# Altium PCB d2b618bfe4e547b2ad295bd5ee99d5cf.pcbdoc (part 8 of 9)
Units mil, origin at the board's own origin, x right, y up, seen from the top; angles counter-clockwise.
Board outline 5129 x 4161 mil, 8 copper layers (Top Layer, GND1, 内层2, VCC, 内层4, Inner5, GND2, Bottom Layer); 491 components, 452 nets, 2562 pads, 1124 vias.
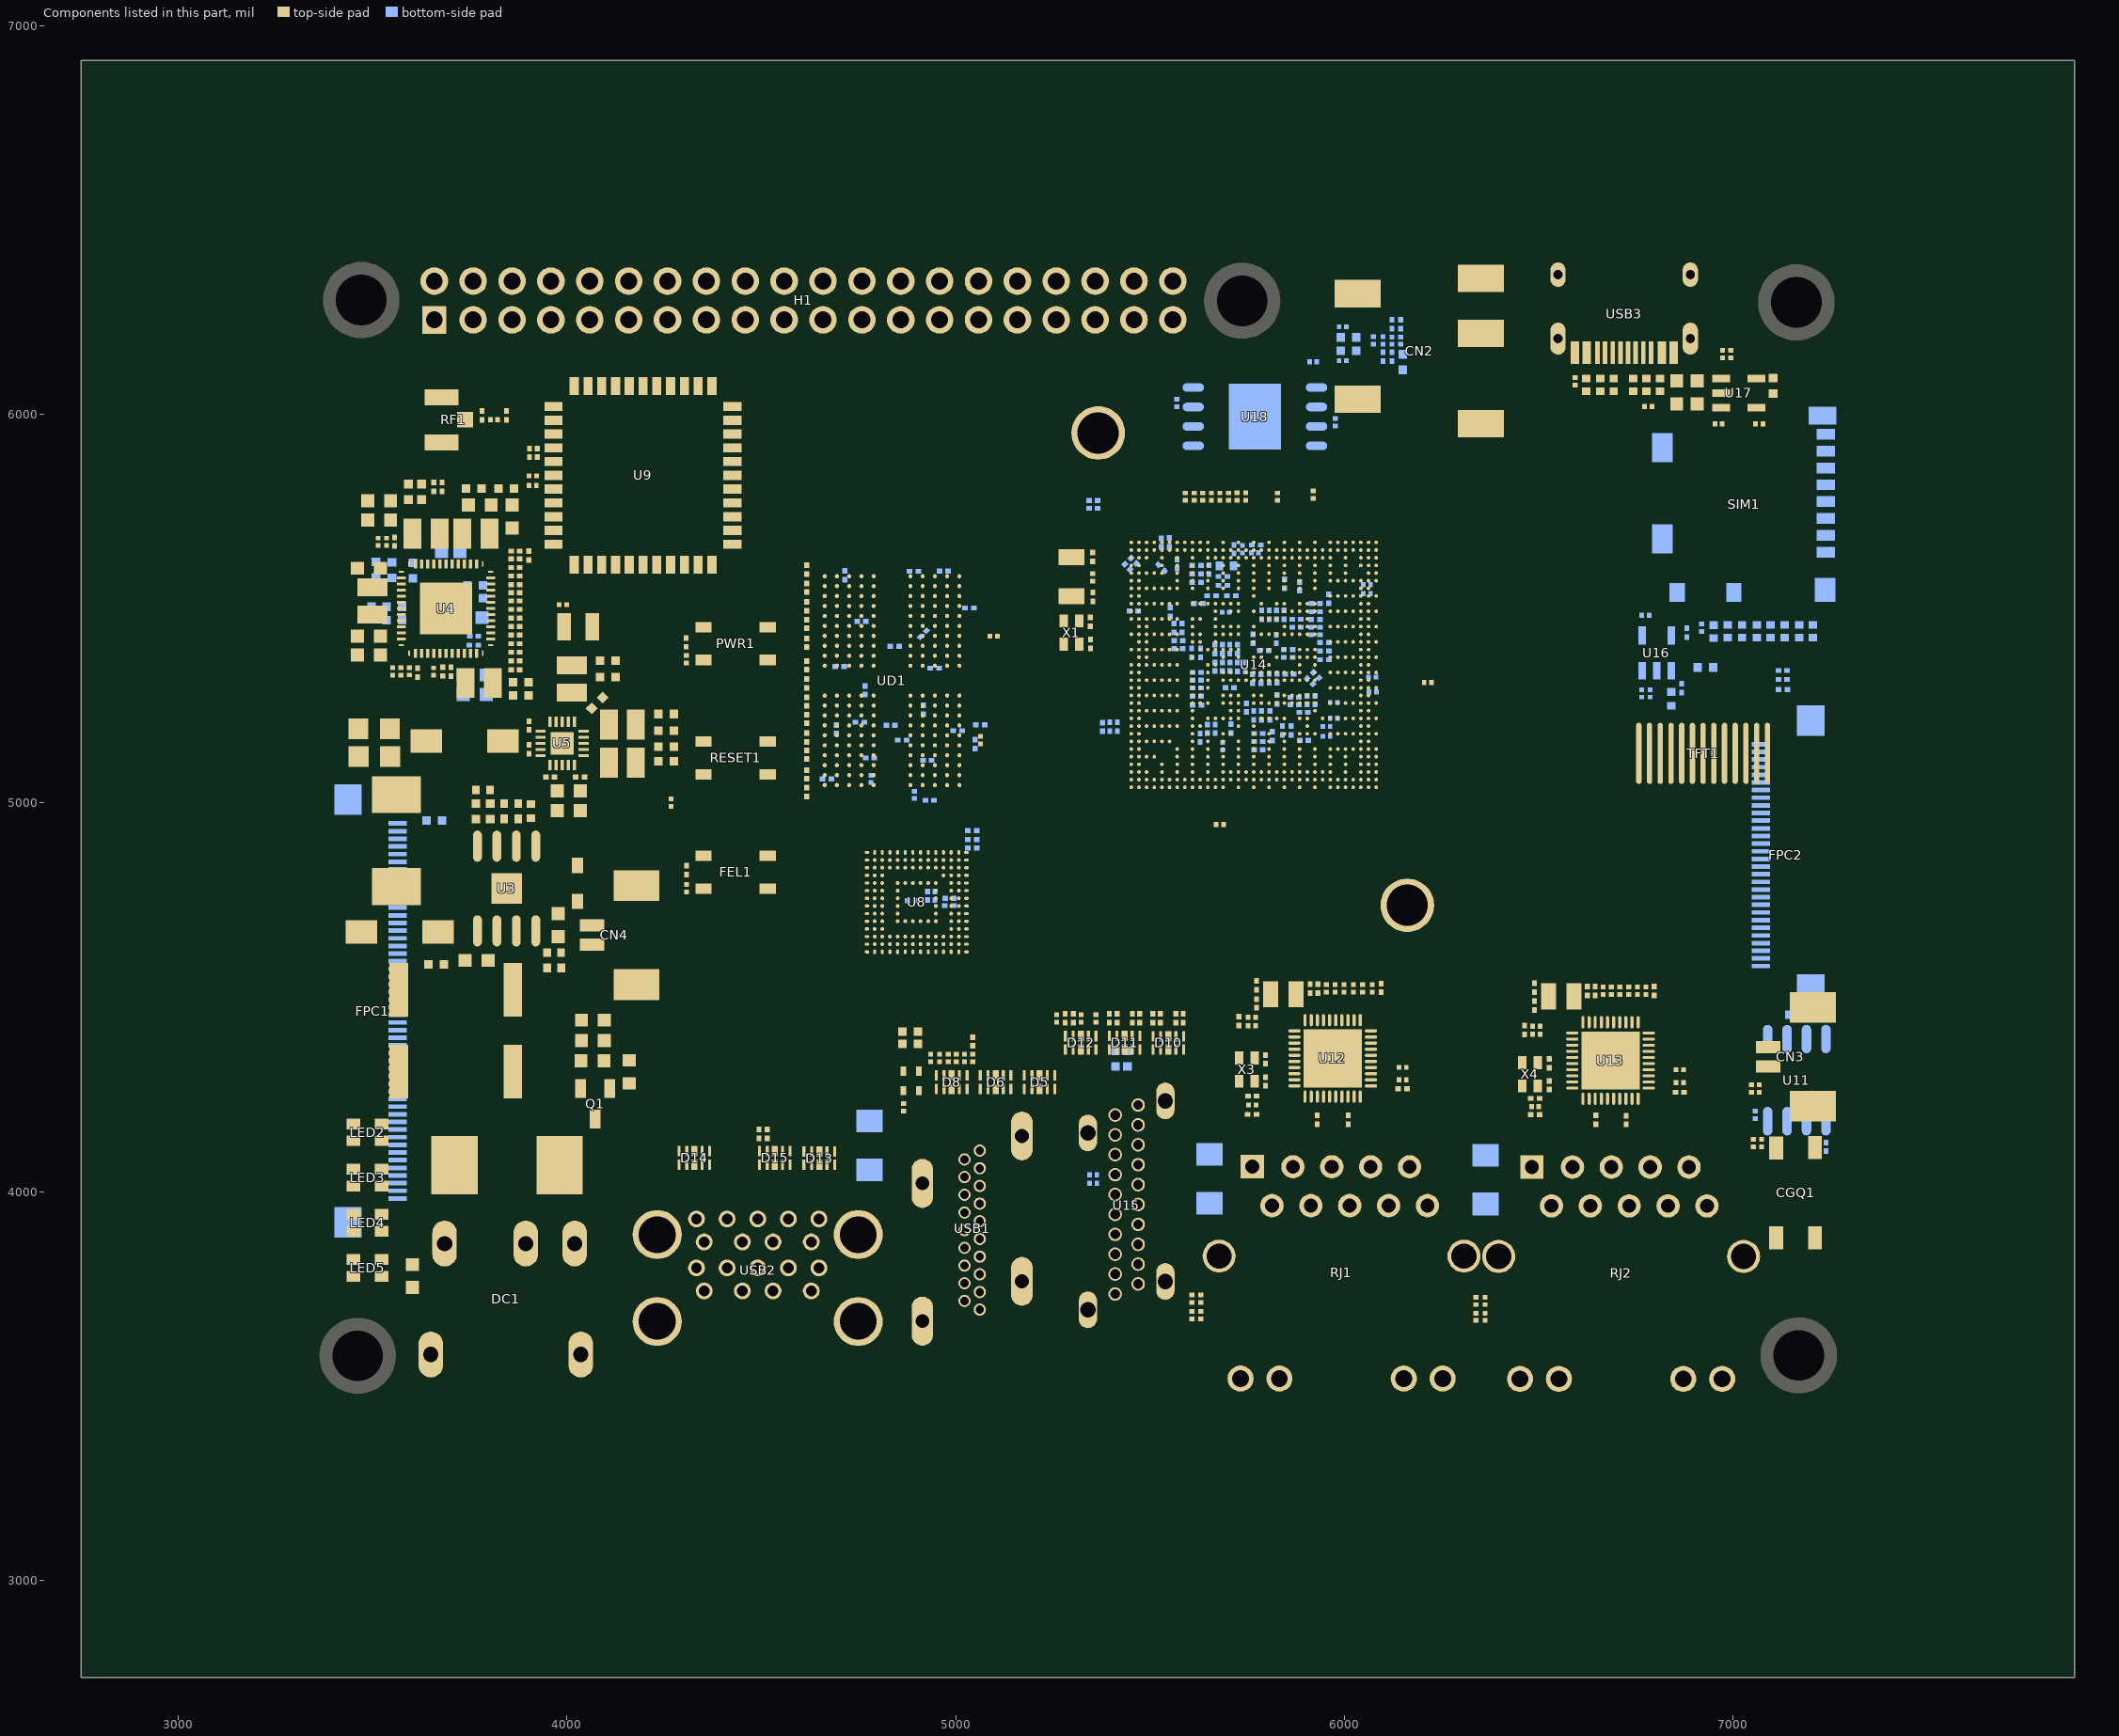
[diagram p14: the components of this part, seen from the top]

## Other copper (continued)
内层2:
  region net CPUX-TX: 3994.66,6310.17 3991.83,6307.34 3984.94,6310.05 3975.43,6309.72 3957.03,6307.62 3994.38,6344.97 3992.28,6326.57 3991.95,6317.06
  region net CPUX-RX: 4094.66,6310.17 4091.83,6307.34 4084.94,6310.05 4075.43,6309.72 4057.03,6307.62 4094.38,6344.97 4092.28,6326.57 4091.95,6317.06
  region net SDQS2N: 4965.15,5507.24 4968.68,5503.71 4969.68,5499.31 4959.73,5505.54 4962.88,5505.8
  region net SDQ19: 5197.07,5492.65 5193.63,5489.73 5190.75,5491.1 5187.23,5491.13 5195.79,5499.17 5195.78,5495.64
  region net SDQ21: 5160.41,5482.63 5151.93,5484.75 5150.11,5486.65 5147.57,5488.19 5159.16,5489.18 5159.3,5486.04
  region net SDQM2: 5087.17,5477.51 5082.67,5479 5081.81,5481.94 5079.43,5484.51 5091.07,5483.02 5088.56,5480.57
  region net SDQ17: 5056.17,5471.21 5051.67,5471.21 5050.54,5474.23 5048.05,5476.73 5059.79,5476.73 5057.3,5474.23
  region net SDQ18: 4889.8,5477.02 4892.98,5480.2 4895.91,5478.87 4899.44,5478.86 4891.14,5470.56 4891.13,5474.09
  region net SDQ16: 5065.36,5433.71 5064.42,5428.29 5057.61,5429.29 5063.37,5439.51 5063.74,5436.09
  region net SAB2: 4782,5413.94 4778.82,5410.75 4775.88,5412.09 4772.36,5412.09 4780.66,5420.39 4780.67,5416.87
  region net SAB0: 5003.12,5386.96 4999.94,5383.77 4997,5385.11 4993.48,5385.11 5001.78,5393.41 5001.79,5389.89
  region net SAB3: 4841.94,5376.17 4845.12,5372.99 4843.79,5370.06 4843.78,5366.54 4835.48,5374.84 4839,5374.84
  region net SAB1: 5071.17,5350.46 5066.67,5350.46 5065.54,5353.48 5063.05,5355.98 5074.79,5355.98 5072.3,5353.48
  region net SCKE0-A: 4861.67,5281.74 4866.17,5281.74 4867.3,5278.72 4869.79,5276.22 4858.05,5276.22 4860.54,5278.72
  region net SDQ23: 5565.13,5266.06 5568.31,5269.24 5571.24,5267.91 5574.77,5267.91 5566.47,5259.61 5566.46,5263.13
  region net SDQ21: 5386.41,5261.3 5394.87,5259.2 5396.7,5257.31 5399.24,5255.78 5387.66,5254.76 5387.52,5257.89
  region net SDQS2P: 5321.42,5259.07 5326.42,5262.05 5330.26,5256.54 5318.91,5253.56 5320.93,5256.23
  region net SDQ22: 5363.27,5261.1 5371.49,5259.25 5373.4,5257.42 5376.01,5255.98 5364.51,5254.55 5364.36,5257.71
  region net SDQ16: 5199.81,5256.56 5203.48,5259.25 5206.3,5257.85 5209.82,5257.8 5201.04,5250 5201.07,5253.53
  region net SDQS2N: 5310.65,5257.24 5312.56,5252.08 5310.78,5249.96 5310.1,5246.74 5305.33,5257.47
  region net SDQM2: 5249.72,5255.99 5252.9,5259.17 5255.83,5257.84 5259.36,5257.84 5251.06,5249.54 5251.05,5253.06
  region net SDQ17: 5228.48,5251.23 5227.93,5258.14 5231.39,5256.95 5234.78,5257.2 5231.09,5246.05 5230.04,5248.96
  region net SAA3: 4748.11,5232.43 4744.93,5229.24 4741.99,5230.58 4738.47,5230.58 4746.77,5238.88 4746.78,5235.36
  region net SCS0-A: 4889.72,5248.99 4892.9,5252.17 4895.83,5250.84 4899.36,5250.84 4891.06,5242.54 4891.05,5246.06
  region net SCKE1-A: 4873.92,5242.22 4873.92,5237.72 4871.28,5236.59 4869.17,5234.11 4869.17,5245.84 4871.28,5243.36
  region net SDQ20: 5480.29,5216.81 5480.29,5221.31 5483.3,5222.45 5485.8,5224.93 5485.8,5213.2 5483.3,5215.68
  region net SDQ18: 5545.13,5229.69 5552.83,5228.35 5554.88,5226.62 5557.61,5225.33 5546.13,5222.89 5546.47,5226.16
  region net SDQ19: 5503.5,5228.21 5509.64,5228.44 5512.11,5227.01 5515.16,5226.17 5504.45,5221.36
  region net SRST: 5568.59,5208.98 5565.41,5212.17 5566.74,5215.1 5566.75,5218.62 5575.05,5210.32 5571.52,5210.32
  region net SDQ23: 5044.76,5606.25 5044.76,5601.75 5041.75,5600.62 5039.25,5598.13 5039.25,5609.87 5041.75,5607.38
  region net SAB2: 5478.41,5181.72 5482.84,5186.22 5485.59,5186.91 5488.36,5188.42 5483.92,5177.55 5481.6,5180.09
  region net SAB1: 5543.77,5185.62 5546.95,5188.8 5549.88,5187.47 5553.41,5187.47 5545.11,5179.17 5545.1,5182.69
  region net SAB0: 5529.74,5170.68 5524.21,5169.39 5524.62,5176.77 5535.6,5172.62 5532.31,5171.97
  region net SAB3: 5505.41,5170.93 5503.29,5173.06 5504.49,5176.19 5504.1,5180.04 5512.4,5171.74 5508.54,5172.14
  region net SDQ1: 4940.6,5178.91 4937.42,5175.72 4934.48,5177.06 4930.96,5177.06 4939.26,5185.36 4939.27,5181.84
  region net SDQ1: 5587.27,5152.14 5584.67,5155.91 5586.08,5158.7 5586.15,5162.22 5593.84,5153.36 5590.32,5153.39
  region net SDQ0: 4907.31,5157.76 4905.62,5153.09 4898.9,5154.16 4905.57,5163.82 4905.78,5160.34
  region net SCS0-A: 5115.59,5164.72 5123.13,5169.22 5125.76,5169.16 5128.64,5169.84 5121.11,5160.98 5118.79,5163.1
  region net SDQ0: 5586.95,5132.03 5583.77,5135.22 5585.1,5138.15 5585.11,5141.67 5593.41,5133.37 5589.88,5133.37
  region net SAA3: 5543.77,5149 5548.12,5148.89 5550.98,5147.79 5554.46,5147.43 5544.23,5141.67 5544.63,5145.43
  region net SCKE1-A: 5072.79,5150.22 5073.54,5154.72 5076.52,5155.72 5079.05,5158.16 5078.31,5146.45 5075.83,5148.96
  region net SCKE0-A: 5147.06,5154.13 5151.56,5154.13 5152.69,5151.11 5155.18,5148.61 5143.44,5148.61 5145.93,5151.11
  region net SDQS0N: 4949.19,5129.29 4950.03,5137.24 4953.64,5141.43 4954.65,5129.86 4952.12,5130.31
  region net SDQS0P: 4938.4,5127.82 4933.4,5123.39 4931.91,5126.59 4929.47,5128.9 4940.34,5133.33 4938.59,5130.56
  region net SDQ2: 5084.38,5113.22 5082.89,5108.72 5079.95,5107.87 5077.38,5105.49 5078.87,5117.13 5081.32,5114.62
  region net SDQ4: 5619.66,5092.53 5619.46,5098.69 5620.89,5101.16 5621.74,5104.21 5626.5,5093.48
  region net SDQ7: 4910.12,5079.96 4906.94,5076.77 4904,5078.11 4900.48,5078.11 4908.78,5086.41 4908.79,5082.89
  region net SDQM0: 4966.6,5076.48 4961.18,5075.53 4958.8,5077.16 4955.38,5077.52 4965.61,5083.28
  region net SDQ6: 5593.1,5067.49 5588.6,5067.49 5587.47,5070.51 5584.98,5073.01 5596.72,5073.01 5594.23,5070.51
  region net SDQ2: 5545.45,5070.33 5543.33,5072.45 5544.53,5075.59 5544.14,5079.44 5552.44,5071.14 5548.59,5071.53
  region net SDQ4: 5094.14,5046.22 5090.78,5041.72 5088,5040.82 5085.27,5039.1 5088.62,5050.35
  region net SDQ6: 5060.94,5055.42 5064.12,5052.24 5062.79,5049.31 5062.78,5045.79 5054.48,5054.09 5058,5054.09
  region net SDQ5: 4939.22,5059.92 4939.02,5055.42 4936.14,5054.76 4933.5,5052.5 4936.01,5063.97 4937.25,5061.4
  region net SDQ3: 5464.9,4986.77 5461.72,4989.96 5463.05,4992.89 5463.06,4996.41 5471.36,4988.11 5467.83,4988.11
  region net SDQS0N: 5526.39,5007.14 5534.57,5006.02 5539.16,5002.81 5527.81,5000.77 5527.56,5003.87
  region net SDQS0P: 5503.06,5002.36 5506.6,5005.89 5509.46,5004.52 5512.88,5004.38 5504.58,4996.08 5504.44,4999.49
  region net SDQ5: 5593.22,4986.12 5588.55,4987.81 5589.62,4994.53 5599.28,4987.86 5595.8,4987.65
  region net SDQM0: 5572.24,4986.13 5567.69,4987.95 5568.82,4991.15 5568.78,4994.65 5578.33,4987.83 5574.84,4987.65
  region net SDQ7: 5617.15,4986.02 5609.63,4984.86 5610.93,4988.38 5610.61,4991.68 5622.02,4988.94 5619.25,4987.71
  region net SDQ20: 4912.89,5549.22 4914.38,5544.72 4911.32,5543.33 4908.87,5540.82 4907.38,5552.46 4909.95,5550.08
  region net SDQ22: 5145.9,5519.77 5142.72,5522.96 5144.05,5525.89 5144.06,5529.41 5152.36,5521.11 5148.83,5521.11
  region net SDQS2P: 4974.93,5519.47 4968.97,5514.47 4963.46,5513.25 4969.42,5523.36 4971.54,5520.91
  region net SRST: 4717.42,5448.17 4720.6,5444.99 4719.27,5442.06 4719.26,5438.54 4710.96,5446.84 4714.48,5446.84
  region net SDQ3: 5146.12,4989.96 5142.94,4986.77 5140,4988.11 5136.48,4988.11 5144.78,4996.41 5144.79,4992.89
  region net CAN-RX0: 5528,5382.37 5532,5382.37 5535.87,5378.25 5524.13,5378.25
  region net CAN-TX0: 5542.01,5383.16 5548.56,5382.26 5550.91,5380.77 5553.92,5379.83 5542.78,5376.14 5543.1,5379.62
  region net VCC-LDO-RTC: 3592,5324.76 3598,5324.76 3600.87,5319.25 3589.13,5319.25
  region net VDD-CPUBFB: 4042.76,5224 4042.76,5214 4039.79,5214.13 4037.25,5213.13 4037.25,5224.87 4039.79,5223.87
  region net RGMII0-CLKIN: 5850.31,4345.41 5847.49,4342.59 5844.84,4343.52 5841.56,4343.04 5849.86,4351.34 5849.38,4348.06
  region net RGMII1-TXD3: 5903.09,5622.14 5907.09,5622.14 5908.3,5619.11 5910.96,5616.63 5899.22,5616.63 5901.88,5619.11
  region net RGMII1-TXD2: 5911.28,5600.72 5914.11,5597.89 5912.82,5594.89 5912.95,5591.25 5904.65,5599.55 5908.28,5599.43
  region net RGMII1-RXCK: 5953.53,5592.3 5955.87,5584.3 5952.38,5585.3 5949.13,5585.36 5950.35,5596.91 5951.75,5594.23
  region net RGMII1-RXD2: 5953.48,5605.18 5950.66,5602.35 5947.66,5603.64 5944.02,5603.52 5952.32,5611.82 5952.19,5608.18
  region net RGMII1-RXD3: 5974.81,5617.89 5977.64,5620.72 5980.64,5619.43 5984.27,5619.55 5975.97,5611.25 5976.1,5614.89
  region net MICIN3N: 5572.5,5720.76 5577.5,5720.76 5578.55,5717.76 5580.87,5715.25 5569.13,5715.25 5571.45,5717.76
  region net MICIN3P: 5593.5,5723.6 5598.5,5723.6 5599.55,5720.6 5601.87,5718.09 5590.13,5718.09 5592.45,5720.6
  region net ALDO4: 5657.7,5804.63 5647.43,5808.5 5649.56,5810.74 5650.72,5813 5661.28,5808.84
  region net RGMII1-CLKIN: 6564.2,4354.44 6567.02,4351.61 6565.73,4348.61 6565.86,4344.97 6557.56,4353.27 6561.2,4353.15
  region net GM1_LED1: 6346.51,3769.27 6342.27,3773.51 6344.14,3779.44 6352.44,3771.14
  region net GM1_LED2: 6312.86,3749 6319,3755 6321.64,3754.69 6324.51,3755.73 6318.37,3746.05 6315.99,3747.8
  region net RGMII0-RXD1: 6017.27,4504.47 6014.44,4507.29 6015.73,4510.29 6015.6,4513.93 6023.9,4505.63 6020.27,4505.76
  region net RGMII0-RXD0: 5998.08,4504.25 5991.16,4502.99 5992.31,4506.56 5991.94,4510 6003.26,4506.87 6000.32,4505.81
  region net RGMII0-RXCTL: 5978,4502.73 5974,4502.73 5972.79,4505.76 5970.13,4508.24 5981.87,4508.24 5979.21,4505.76
  region net RGMII0-RXCK: 5963.02,4507.29 5960.2,4504.47 5957.2,4505.76 5953.56,4505.63 5961.86,4513.93 5961.73,4510.29
  region net EDP-TX3N: 5392.5,4486.37 5397.5,4486.37 5398.55,4483.57 5400.87,4481.25 5389.13,4481.25 5391.45,4483.57
  region net EDP-TX3P: 5413.5,4486.37 5418.5,4486.37 5419.55,4483.57 5421.87,4481.25 5410.13,4481.25 5412.45,4483.57
  region net RGMII0-TXCTL: 5992.55,5428.33 5989.72,5425.5 5986.72,5426.79 5983.09,5426.67 5991.39,5434.97 5991.26,5431.33
  region net RGMII0-TXD0: 6009.4,5404.19 6012.23,5401.36 6010.94,5398.36 6011.07,5394.72 6002.77,5403.02 6006.4,5402.9
  region net PHYRSTB0: 6033.65,5397.16 6033.65,5393.16 6030.62,5391.95 6028.14,5389.29 6028.14,5401.03 6030.62,5398.37
  region net RGMII0-RXCTL: 6029.08,5364.8 6031.91,5361.97 6030.62,5358.97 6030.75,5355.34 6022.45,5363.64 6026.08,5363.51
  region net RGMII0-RXD0: 6005.2,5346.9 6001.2,5346.9 5999.63,5348.85 5997.33,5350.53 6009.07,5350.53 6006.78,5348.85
  region net RGMII0-RXD1: 5991.42,5345.41 5984.65,5346.53 5982.36,5348.06 5979.39,5349.07 5990.64,5352.42 5990.29,5348.97
  region net EDP-HPD: 6033.33,5121.75 6033.33,5116.75 6030.33,5115.7 6027.82,5113.38 6027.82,5125.12 6030.33,5122.81
  region net CTP-RST: 5828.84,5088.8 5823.84,5088.8 5822.79,5091.8 5820.48,5094.31 5832.21,5094.31 5829.9,5091.8
  region net LCD0-D0: 5859.88,5129.56 5856.34,5133.09 5857.71,5135.95 5857.85,5139.37 5866.15,5131.07 5862.74,5130.93
  region net LCD0-D1: 5875.35,5117.18 5874.83,5110.64 5871.52,5111.83 5868.16,5111.76 5872.88,5122.5 5873.57,5119.29
  region net LCD0-VSYNC: 5894.33,5116.75 5894.33,5121.75 5897.32,5122.8 5899.84,5125.12 5899.84,5113.38 5897.32,5115.69
  region net RGMII0-TXD3: 6181.02,5395.8 6178.2,5392.98 6175.2,5394.27 6171.56,5394.14 6179.86,5402.44 6179.73,5398.8
  region net RGMII0-TXD2: 6160.02,5395.8 6157.2,5392.98 6154.2,5394.27 6150.56,5394.14 6158.86,5402.44 6158.73,5398.8
  region net RGMII0-RXCK: 6139.02,5395.8 6136.2,5392.98 6133.2,5394.27 6129.56,5394.14 6137.86,5402.44 6137.73,5398.8
  region net RGMII0-MDIO: 6200.2,5410.02 6203.02,5407.2 6201.73,5404.2 6201.86,5400.56 6193.56,5408.86 6197.2,5408.73
  region net RGMII0-MDC: 6222.2,5410.02 6225.02,5407.2 6223.73,5404.2 6223.86,5400.56 6215.56,5408.86 6219.2,5408.73
  region net RGMII0-TXD1: 6249.02,5394.8 6246.2,5391.98 6243.2,5393.27 6239.56,5393.14 6247.86,5401.44 6247.73,5397.8
  region net RGMII0-CLKIN: 6276.01,5398 6270.05,5394 6267.37,5393.56 6264.54,5392.28 6270.5,5402.39 6272.64,5399.7
  region net RGMII0-TXD1: 6119.02,4363.8 6116.2,4360.98 6113.2,4362.27 6109.56,4362.14 6117.86,4370.44 6117.73,4366.8
  region net RGMII0-MDC: 6205.2,4315.02 6208.02,4312.2 6206.73,4309.2 6206.86,4305.56 6198.56,4313.86 6202.2,4313.73
  region net RGMII0-MDIO: 6224,4327.13 6228,4331.6 6232.43,4326.09 6221.57,4321.62 6223.22,4324.38
  region net RGMII0-TXD3: 6163,4389.76 6167,4389.76 6168.21,4386.73 6170.87,4384.25 6159.13,4384.25 6161.79,4386.73
  region net RGMII0-TXD2: 6148.2,4388.02 6151.02,4385.2 6149.73,4382.2 6149.86,4378.56 6141.56,4386.86 6145.2,4386.73
  region net PHYRSTB0: 6129.96,4289.9 6129.96,4285.9 6126.92,4284.69 6124.45,4282.03 6124.45,4293.77 6126.92,4291.11
  region net RGMII0-TXD0: 6323,4395.76 6327,4395.76 6328.21,4392.73 6330.87,4390.25 6319.13,4390.25 6321.79,4392.73
  region net RGMII0-TXCTL: 6354.2,4410.02 6357.02,4407.2 6355.73,4404.2 6355.86,4400.56 6347.56,4408.86 6351.2,4408.73
  region net RGMII0-TXCK: 6371,4412.76 6375,4412.76 6376.21,4409.73 6378.87,4407.25 6367.13,4407.25 6369.79,4409.73
  region net RGMII0-TXCK: 5969.55,5443.67 5971.67,5441.55 5970.47,5438.41 5970.86,5434.56 5962.56,5442.86 5966.41,5442.47
  region net EDP-TX2P: 5471.5,4488.37 5476.5,4488.37 5477.55,4485.57 5479.87,4483.25 5468.13,4483.25 5470.45,4485.57
  region net EDP-TX2N: 5451.5,4488.37 5456.5,4488.37 5457.55,4485.57 5459.87,4483.25 5448.13,4483.25 5450.45,4485.57
  region net EDP-TX1N: 5503.5,4486.37 5508.5,4486.37 5511.87,4483.25 5500.13,4483.25
  region net EDP-TX1P: 5525.5,4486.58 5530.5,4486.58 5531.55,4484.17 5533.87,4482.25 5522.13,4482.25 5524.45,4484.17
  region net EDP-TX0N: 5563.5,4486.37 5568.5,4486.37 5569.55,4484.07 5571.87,4482.25 5560.13,4482.25 5562.45,4484.07
  region net EDP-TX0P: 5584.5,4485.58 5589.5,4485.58 5592.87,4482.25 5581.13,4482.25
  region net EDP-AUXP: 5288.48,4469.43 5283.48,4463.49 5282.05,4466.88 5279.59,4469 5289.72,4474.94
  region net EDP-AUXN: 5297.16,4467.12 5293.62,4470.66 5295,4473.52 5295.14,4476.94 5303.44,4468.64 5300.02,4468.5
  region net RGMII1-RXCK: 6664,4518.25 6668,4518.25 6669.21,4515.22 6671.87,4512.74 6660.13,4512.74 6662.79,4515.22
  region net RGMII1-RXCTL: 6685,4518.25 6689,4518.25 6690.21,4515.22 6692.87,4512.74 6681.13,4512.74 6683.79,4515.22
  region net RGMII1-RXD0: 6707,4518.25 6711,4518.25 6712.21,4515.22 6714.87,4512.74 6703.13,4512.74 6705.79,4515.22
  region net RGMII1-RXD1: 6730,4518.25 6734,4518.25 6735.21,4515.22 6737.87,4512.74 6726.13,4512.74 6728.79,4515.22
  region net RGMII1-RXD2: 6752,4518.25 6756,4518.25 6757.21,4515.22 6759.87,4512.74 6748.13,4512.74 6750.79,4515.22
  region net RGMII1-RXD3: 6774,4518.25 6778,4518.25 6779.21,4515.22 6781.87,4512.74 6770.13,4512.74 6772.79,4515.22
  region net RGMII1-TXCK: 6793.98,4454.2 6796.8,4457.02 6799.8,4455.73 6803.44,4455.86 6795.14,4447.56 6795.27,4451.2
  region net RGMII1-TXCTL: 6815.98,4454.2 6818.8,4457.02 6821.8,4455.73 6825.44,4455.86 6817.14,4447.56 6817.27,4451.2
  region net RGMII1-TXD0: 6837.98,4454.2 6840.8,4457.02 6843.8,4455.73 6847.44,4455.86 6839.14,4447.56 6839.27,4451.2
  region net RGMII1-TXD1: 6860.98,4454.2 6863.8,4457.02 6866.8,4455.73 6870.44,4455.86 6862.14,4447.56 6862.27,4451.2
  region net RGMII1-TXD2: 6882.98,4454.2 6885.8,4457.02 6888.8,4455.73 6892.44,4455.86 6884.14,4447.56 6884.27,4451.2
  region net RGMII1-TXD3: 6862,4381.76 6866,4381.76 6867.21,4378.73 6869.87,4376.25 6858.13,4376.25 6860.79,4378.73
  region net RGMII1-MDIO: 6871.2,4354.02 6874.02,4351.2 6872.73,4348.2 6872.86,4344.56 6864.56,4352.86 6868.2,4352.73
  region net PHYRSTB1: 6848.76,4281 6848.76,4277 6845.73,4275.79 6843.25,4273.13 6843.25,4284.87 6845.73,4282.21
  region net RGMII1-MDC: 6919,4365 6919,4361 6916.35,4359.79 6914.25,4357.13 6914.25,4368.87 6916.35,4366.21
  region net RGMII1-RXD0: 6640.14,5605.69 6638.05,5602.12 6634.89,5603.3 6631.27,5603.13 6638.79,5612.14 6638.75,5608.52
  region net RGMII1-RXD1: 6661.02,5606.8 6658.2,5603.98 6655.2,5605.27 6651.56,5605.14 6659.86,5613.44 6659.73,5609.8
  region net RGMII1-TXD0: 6720.02,5630.8 6717.2,5627.98 6714.2,5629.27 6710.56,5629.14 6718.86,5637.44 6718.73,5633.8
  region net RGMII1-TXD1: 6748.02,5639.8 6745.2,5636.98 6742.2,5638.27 6738.56,5638.14 6746.86,5646.44 6746.73,5642.8
  region net RGMII1-TXCTL: 6756,5581.24 6752,5581.24 6750.79,5584.27 6748.13,5586.75 6759.87,5586.75 6757.21,5584.27
  region net RGMII1-TXCK: 6745,5544.9 6741,5541.92 6736.66,5547.43 6748.01,5550.41 6746.07,5547.7
  region net RGMII1-MDIO: 6836.02,5470.8 6833.2,5467.98 6830.2,5469.27 6826.56,5469.14 6834.86,5477.44 6834.73,5473.8
  region net RGMII1-MDC: 6856.2,5486.02 6859.02,5483.2 6857.73,5480.2 6857.86,5476.56 6849.56,5484.86 6853.2,5484.73
  region net PHYRSTB1: 6866.8,5467.98 6863.98,5470.8 6865.27,5473.8 6865.14,5477.44 6873.44,5469.14 6869.8,5469.27
  region net RGMII1-CLKIN: 6624,5564.24 6620,5564.24 6618.79,5567.27 6616.13,5569.75 6627.87,5569.75 6625.21,5567.27
  region net RGMII1-RXCTL: 6665.02,5519.8 6662.2,5516.98 6659.2,5518.27 6655.56,5518.14 6663.86,5526.44 6663.73,5522.8
  region net EDP-TX0N: 6311.52,4748.95 6311.28,4756.25 6314.66,4754.94 6317.95,4755.13 6314.33,4743.96
  region net EDP-TX0P: 6304.5,4744 6309.5,4742.05 6309.95,4739.23 6311.94,4736.54 6300.64,4739.72
  region net EDP-TX1P: 6290.91,4846.56 6299.02,4845.52 6303.65,4842.35 6292.33,4840.19 6292.08,4843.29
  region net EDP-TX1N: 6302.75,4848.5 6302.75,4853.5 6304.99,4854.55 6306.75,4856.87 6306.75,4845.13 6304.99,4847.45
  region net EDP-AUXP: 5669.31,4463.77 5671.77,4473.31 5675.89,4476.99 5675.63,4465.24 5672.67,4465.01
  region net EDP-AUXN: 5670.5,4478.75 5665.5,4478.75 5662.13,4481.75 5673.87,4481.75
  region net EDP-HPD: 5365.84,4502.38 5369.38,4498.84 5368,4495.98 5367.86,4492.56 5359.56,4500.86 5362.98,4501
  region net HBIAS: 5877.14,6193.93 5870.07,6186.86 5868.07,6189.05 5865.56,6190.14 5873.86,6198.44 5874.95,6195.93
  region net HBIAS: 6163.24,6149.49 6163.24,6159.49 6166.21,6159.36 6168.75,6160.36 6168.75,6148.62 6166.21,6149.62
  region net LCD0-RST: 5852.24,4928.5 5852.24,4933.5 5855.24,4934.55 5857.75,4936.87 5857.75,4925.13 5855.24,4927.45
  region net LCD0-PWM: 5866.24,4944.5 5866.24,4949.5 5869.24,4950.55 5871.75,4952.87 5871.75,4941.13 5869.24,4943.45
  region net LCD0-D3: 4729.38,4746.16 4725.84,4742.62 4722.98,4744 4719.56,4744.14 4727.86,4752.44 4728,4749.02
  region net LCD0-D2: 4729.38,4770.16 4725.84,4766.62 4722.98,4768 4719.56,4768.14 4727.86,4776.44 4728,4773.02
  region net LCD0-D1: 4728.38,4795.16 4724.84,4791.62 4721.98,4793 4718.56,4793.14 4726.86,4801.44 4727,4798.02
  region net LCD0-D0: 4728.38,4818.16 4724.84,4814.62 4721.98,4816 4718.56,4816.14 4726.86,4824.44 4727,4821.02
  region net LCD0-D3: 6035.16,4935.62 6031.62,4939.16 6033,4942.02 6033.14,4945.44 6041.44,4937.14 6038.02,4937
  region net LCD0-D2: 6044.24,4958.5 6044.24,4963.5 6047.24,4964.55 6049.75,4966.87 6049.75,4955.13 6047.24,4957.45
  region net LCD0-PWM: 4452.5,4441.76 4457.5,4441.76 4458.55,4438.76 4460.87,4436.25 4449.13,4436.25 4451.45,4438.76
  region net LCD0-RST: 4467.5,4424.76 4472.5,4424.76 4473.55,4421.76 4475.87,4419.25 4464.13,4419.25 4466.45,4421.76
  region net CTP-RST: 4330.76,4378.5 4330.76,4373.5 4327.76,4372.45 4325.25,4370.13 4325.25,4381.87 4327.76,4379.55
  region net LCD0-VSYNC: 4261.76,4307.5 4261.76,4302.5 4258.76,4301.45 4256.25,4299.13 4256.25,4310.87 4258.76,4308.55
  region net DCDC4: 5897.54,5286.34 5891.92,5299.11 5895.58,5299.15 5898.09,5300.72 5901.83,5289.82 5899.73,5288.56
  region net DCDC4: 5898.5,5306.42 5911.5,5306.42 5912.85,5297 5897.15,5297
  region net VDD-CPUBFB: 5817.08,5262.04 5817.08,5252.04 5814.12,5252.18 5811.59,5251.19 5811.59,5262.89 5814.12,5261.9
  region net VCC-LDO-RTC: 3598,5424.71 3592,5432.25 3592.72,5434.78 3592.15,5437.75 3600.93,5430.21 3599.22,5427.91
  region net DCDC4: 5896.26,5390.94 5887.06,5381.74 5879.45,5387.45 5890.55,5398.55
  region net BLDO3: 5876.73,5478 5876.73,5468 5873.76,5468.14 5871.23,5467.15 5871.23,5478.85 5873.76,5477.86
  region net SPI-LCD-RST: 5170.5,6019.73 5175.5,6019.73 5176.55,6016.74 5178.85,6014.23 5167.15,6014.23 5169.45,6016.74
  region net SPI-LCD-BLK: 5199.53,5998.07 5198.49,5989.96 5195.33,5985.35 5193.19,5996.64 5196.28,5996.89
  region net SPI-LCD-CS: 5216.3,5982.83 5217.6,5977.06 5215.92,5974.75 5215.43,5971.46 5209.7,5981.66
  region net SPI-LCD-CLK: 5233.82,5968.35 5237.35,5964.82 5235.98,5961.97 5235.84,5958.56 5227.56,5966.84 5230.97,5966.98
  region net SPI-LCD-MOSI: 5248.5,5956.29 5253.5,5948.75 5253.85,5943.25 5245.04,5950.79 5247.02,5953.09
  region net SPI-LCD-DC: 5263.5,5938.73 5268.5,5938.73 5269.55,5935.74 5271.85,5933.23 5260.15,5933.23 5262.45,5935.74
  region net FEL: 4108.71,5786.54 4104.46,5782.29 4098.56,5784.16 4106.84,5792.44
  region net GM1_LED1: 6556.09,4366.18 6550.09,4366.18 6547.24,4371.68 6558.94,4371.68
  region net GM1_LED2: 6524.52,4357.29 6520.27,4361.54 6522.14,4367.44 6530.42,4359.16
  region net MICIN3P: 5941.65,5857.82 5945.18,5861.35 5948.03,5859.98 5951.44,5859.84 5943.16,5851.56 5943.02,5854.97
  region net MICIN3N: 5945.25,5869.5 5937.71,5874.5 5940.91,5875.98 5943.21,5877.96 5950.75,5869.15
  region net SPI-LCD-BLK: 7003.5,5600.73 7008.5,5600.73 7009.55,5597.74 7011.85,5595.23 7000.15,5595.23 7002.45,5597.74
  region net SPI-LCD-MOSI: 6945.65,5319.82 6949.18,5323.35 6952.03,5321.98 6955.44,5321.84 6947.16,5313.56 6947.02,5316.97
  region net SPI-LCD-DC: 6950.5,5288.73 6955.5,5288.73 6956.55,5285.74 6958.85,5283.23 6947.15,5283.23 6949.45,5285.74
  region net SPI-LCD-CLK: 6969.5,5269.94 6974.5,5271.43 6978.14,5265.94 6966.53,5264.45 6968.73,5267.02
  region net SPI-LCD-RST: 6958.77,5221.77 6955.23,5218.23 6950.56,5218.16 6958.84,5226.44
  region net SPI-LCD-CS: 6932.82,5252.35 6936.35,5248.82 6934.98,5245.97 6934.84,5242.56 6926.56,5250.84 6929.97,5250.98
  region net CPUX-RX: 6790.2,6120.98 6793.02,6123.8 6796.01,6122.52 6799.63,6122.64 6791.36,6114.37 6791.48,6117.99
  region net CPUX-TX: 6668.79,6122.09 6672.79,6122.09 6673.99,6119.07 6676.64,6116.6 6664.94,6116.6 6667.59,6119.07
  region net IR-RX: 5503.59,5380.59 5506.41,5383.41 5508.77,5383.27 5511.44,5383.84 5503.16,5375.56 5503.73,5378.23
  region net USB0-VBUSDET: 5580,5339.17 5582.83,5342 5585.82,5340.71 5589.44,5340.84 5581.16,5332.56 5581.29,5336.18
  region net USB0-DRVVBUS: 5580,5316.17 5582.83,5319 5585.82,5317.71 5589.44,5317.84 5581.16,5309.56 5581.29,5313.18
  region net CAN-TX0: 5167.04,5729.13 5164.47,5726.05 5161.42,5727.3 5157.81,5727.15 5165.82,5735.68 5165.72,5732.06
  region net CAN-RX0: 5144,5727.83 5141.17,5725 5138.18,5726.29 5134.56,5726.16 5142.84,5734.44 5142.71,5730.82
  region net IR-RX: 5121,5725.83 5118.17,5723 5115.18,5724.29 5111.56,5724.16 5119.84,5732.44 5119.71,5728.82
  region net USB0-VBUSDET: 5095,5725.83 5092.17,5723 5089.18,5724.29 5085.56,5724.16 5093.84,5732.44 5093.71,5728.82
  region net USB0-DRVVBUS: 5072,5722.83 5069.17,5720 5066.18,5721.29 5062.56,5721.16 5070.84,5729.44 5070.71,5725.82
  region net LEDC: 6552.65,5366.47 6550.53,5364.35 6547.4,5365.55 6543.56,5365.16 6551.84,5373.44 6551.45,5369.6
  region net LEDC: 3459.65,4200.47 3457.53,4198.35 3454.4,4199.55 3450.56,4199.16 3458.84,4207.44 3458.45,4203.6
  region net BLDO3: 6107.27,5531 6107.27,5541 6110.24,5540.86 6112.77,5541.85 6112.77,5530.15 6110.24,5531.14
  region net EDP-TX3N: 6178.18,4964.65 6174.65,4968.18 6176.02,4971.03 6176.16,4974.44 6184.44,4966.16 6181.03,4966.02
  region net EDP-TX2N: 6221.25,4929.5 6213.71,4934.5 6216.91,4935.98 6219.21,4937.96 6226.75,4929.15
  region net EDP-TX2P: 6232.27,4919.5 6232.27,4924.5 6235.26,4925.55 6237.77,4927.85 6237.77,4916.15 6235.26,4918.45
  region net FEL: 4235.29,5449.46 4239.54,5453.71 4245.44,5451.84 4237.16,5443.56
  region net EDP-TX3P: 6195.77,4955.23 6192.23,4958.77 6193.31,4961.33 6193.16,4964.44 6201.44,4956.16 6198.33,4956.31
  region net DCDC4: 5618.92,5381.66 5618.92,5368.66 5609.5,5367.31 5609.5,5383.01
  region net SAB3: 5458.02,5175.47 5458.02,5172.47 ccw(c5458.02,5037.44) 5453.52,5172.4 5453.52,5175.55 ccw(c5458.02,5310.51)
  region net SDQ1: 5487.98,5060.04 5485.86,5057.91 ccw(c5453.08,5025.14) 5483.94,5059.72 5486.17,5061.95 ccw(c5520.75,5092.81)
  region net SDQ1: 5545.98,5057.91 5543.86,5060.04 ccw(c5511.08,5092.81) 5545.67,5061.95 5547.89,5059.72 ccw(c5578.76,5025.14)
  region net SAB0: 5480.02,5162.47 5480.02,5159.47 ccw(c5480.02,5024.44) 5475.52,5159.4 5475.52,5162.55 ccw(c5480.02,5297.51)
  region net SAA3: 5472.17,5151.35 5474.3,5149.23 ccw(c5569.78,5053.75) 5471.17,5146 5468.94,5148.22 ccw(c5376.69,5246.84)
VCC:
  region net DCDC4: 3536.68,5559.03 3493.65,5516 3474,5516 3454,5536 3454,5558.59 3490.41,5595 3522.93,5595 3536.68,5581.24
  region net DCDC4: 3621.43,6170.07 3590.51,6209.86 ccw(c3492.24,6308.13) 3628,6278.43 3690,6207.57 ccw(c3719.7,6071.8)
  region net DCDC4: 4442.44,6191.08 4407.08,6226.44 4418.19,6234.44 4421.92,6238.34 4423.62,6244.97 4460.97,6207.62 4454.34,6205.92 4450.44,6202.19
  region net PE6: 4594.39,6208.44 4590.07,6207.1 4583.32,6209.97 4573.95,6209.65 4555.62,6207.73 4594.43,6243.56 4592.19,6225.11 4591.85,6215.44
  region net PE1: 4694.78,6211.05 4692.7,6207.47 4685.75,6210.09 4676.16,6209.76 4657.73,6207.59 4694.33,6245.68 4692.32,6227.31 4692,6217.87
  region net PE5: 4628.82,6306.99 4623.76,6307.58 4626.2,6314.64 4625.87,6324.38 4623.57,6342.85 4663.09,6307.8 4654.67,6308.21 4644.79,6309.63 4635.49,6309.94
  region net PE8: 4791.25,6195.58 4775,6206.17 4772.92,6208.76 4769.81,6210.08 4761.58,6210.28 4752.43,6209.55 4744.45,6210.69 4792.73,6232.13 4788.74,6213.68 4788.88,6204.35
  region net PE7: 4725.3,6307.47 4723.22,6311.05 4726,6317.87 4725.68,6327.31 4723.67,6345.68 4760.27,6307.59 4741.84,6309.76 4732.25,6310.09
  region net PE12: 4826.17,6307.34 4823.34,6310.17 4826.05,6317.06 4825.72,6326.57 4823.62,6344.97 4860.97,6307.62 4842.57,6309.72 4833.06,6310.05
  region net DCDC4: 5420.34,4221.38 5434.48,4207.24 5430.15,4202.32 5427.97,4196.43 5409.53,4214.87 5415.42,4217.05
  region net ALDO4: 5621.69,5207.44 5636.69,5207.44 5637.06,5197.99 5621.31,5197.99
  region net ALDO3: 3557.26,5324.73 3561.5,5320.49 3559.63,5314.56 3551.33,5322.86
  region net ALDO4: 5665.5,5806.55 5650.5,5806.55 5650.13,5816 5665.87,5816
  region net USB0-DP: 6327.5,5223.37 6332.5,5223.37 6333.55,5220.57 6335.87,5218.25 6324.13,5218.25 6326.45,5220.57
  region net USB0-DM: 6307.5,5220.76 6312.5,5220.76 6313.55,5217.76 6315.87,5215.25 6304.13,5215.25 6306.45,5217.76
  region net DCDC4: 6842.76,4263 6842.76,4253 6839.79,4253.13 6837.25,4252.13 6837.25,4263.87 6839.79,4262.87
  region net FEL: 5972.76,5392.16 5972.76,5398.16 5978.27,5401.03 5978.27,5389.29
  region net DCDC4: 5892.5,5168.77 5877.5,5168.94 5877.21,5178.39 5892.96,5178.22
  region net DCDC4: 5886.47,5190.29 5897.07,5179.68 5890.66,5172.74 5879.52,5183.87
  region net PE12: 6089.8,5758.98 6086.98,5761.8 6088.27,5764.8 6088.14,5768.44 6096.44,5760.14 6092.8,5760.27
  region net PE8: 6178.8,5757.98 6175.98,5760.8 6177.27,5763.8 6177.14,5767.44 6185.44,5759.14 6181.8,5759.27
  region net PE7: 6209,5757.24 6205,5757.24 6203.79,5760.27 6201.13,5762.75 6212.87,5762.75 6210.21,5760.27
  region net PE5: 6156.9,5708 6153.92,5712 6159.43,5716.34 6162.41,5704.99 6159.7,5706.93
  region net PE6: 6183.61,5702.78 6179.29,5704.12 6180.36,5707.42 6180.19,5711.02 6189.84,5704.34 6186.25,5704.27
  region net PE1: 6199.98,5718.2 6202.8,5721.02 6205.8,5719.73 6209.44,5719.86 6201.14,5711.56 6201.27,5715.2
  region net CLDO3: 7136.07,5504.54 7143.14,5497.47 7140.95,5495.47 7139.86,5492.96 7131.56,5501.26 7134.07,5502.35
  region net DCDC4: 7040.24,4149 7040.24,4159 7043.21,4158.87 7045.75,4159.87 7045.75,4148.13 7043.21,4149.13
  region net DCDC4: 3523.45,5692.88 3527.75,5698.88 3530.5,5698.95 3533.26,5700.38 3528.97,5689.46 3526.67,5691.67
  region net AP-RESET: 3991,5064.24 3985,5064.24 3982.13,5069.75 3993.87,5069.75
  region net USB0-DP: 6726.77,6011.23 6723.23,6014.77 6724.3,6017.33 6724.14,6020.44 6732.44,6012.14 6729.33,6012.3
  region net USB0-DM: 6717.77,6014.77 6714.23,6011.23 6711.67,6012.3 6708.56,6012.14 6716.86,6020.44 6716.7,6017.33
  region net ALDO4: 5739.6,5550.94 5728.99,5540.34 5722.05,5546.75 5733.18,5557.89
  region net ALDO4: 5718.17,5544.82 5718.17,5559.82 5727.62,5560.19 5727.62,5544.45
  region net DCDC4: 5329,4480.27 5319,4480.27 5319.14,4483.24 5318.15,4485.77 5329.85,4485.77 5328.86,4483.24
  region net DCDC4: 5912.5,5287.58 5897.5,5287.58 5897.15,5297 5912.85,5297
  region net DCDC4: 5897.5,5306.42 5912.5,5306.42 5912.85,5297 5897.15,5297
  region net DCDC4: 5931.5,5288.53 5916.5,5285.01 5919.24,5288.06 5920.6,5290.5 5932.27,5294.03
  region net VDD-DNRFB: 5664.5,5423.09 5657.43,5430.16 5659.63,5432.16 5660.71,5434.65 5668.99,5426.38 5666.5,5425.29
  region net VDD-DNRFB: 3956.05,5279.12 3963.12,5272.05 3960.92,5270.06 3959.84,5267.56 3951.56,5275.84 3954.06,5276.92
  region net CLDO3: 5585.64,6062.23 5592.72,6055.15 5590.52,6053.16 5589.43,6050.67 5581.16,6058.94 5583.65,6060.03
  region net DCDC4: 5894.96,5513.64 5884.36,5503.04 5877.45,5509.45 5888.55,5520.55
  region net AP-RESET: 3619.5,5401.57 3614.5,5403.06 3613.73,5405.98 3611.53,5408.55 3623.14,5407.06
  region net AP-NMI: 3642,5399.95 3636,5402.94 3635.67,5405.75 3634.01,5408.43 3645.32,5405.45
  region net AP-NMI: 3632,5418.17 3634.83,5421 3637.82,5419.71 3641.44,5419.84 3633.16,5411.56 3633.29,5415.18
  region net AP-NMI: 3639.83,5580 3637,5582.83 3638.29,5585.82 3638.16,5589.44 3646.44,5581.16 3642.82,5581.29
  region net ALDO3: 3846.79,5415.46 3851.04,5419.71 3856.94,5417.84 3848.66,5409.56
  region net BLDO3: 3857.86,5531.96 3868.46,5521.36 3862.05,5514.45 3850.95,5525.55
  region net AP-RESET: 3915.98,5197.5 3910.02,5202.5 3913.41,5203.93 3915.52,5206.37 3921.48,5196.3
  region net BLDO1: 5587.64,5559.04 5577.04,5569.64 5583.45,5576.55 5594.55,5565.45
  region net FEL: 4109.73,5795 4109.73,5789 4104.23,5786.15 4104.23,5797.85
  region net AP-NMI: 3636,5360.73 3642,5360.73 3644.85,5355.23 3633.15,5355.23
  region net CPUX-RX: 6801.2,6104.07 6797.2,6104.07 6795.99,6107.1 6793.35,6109.57 6805.05,6109.57 6802.4,6107.1
  region net CPUX-TX: 6660.06,6109.36 6660.06,6113.36 6663.09,6114.57 6665.56,6117.21 6665.56,6105.51 6663.09,6108.16
  region net ALDO4: 5754.5,5475.42 5739.5,5475.42 5739.15,5484.84 5754.85,5484.84
  region net ALDO4: 5739.5,5494.26 5754.5,5494.26 5754.85,5484.84 5739.15,5484.84
  region net CPUX-RX: 6296,5262.73 6300,5262.73 6301.2,5259.7 6303.85,5257.23 6292.15,5257.23 6294.8,5259.7
  region net CPUX-TX: 6284.17,5272 6287,5269.17 6285.71,5266.18 6285.84,5262.56 6277.56,5270.84 6281.18,5270.71
  region net DCDC4: 6105.04,4255 6098.88,4265 6102.05,4265.13 6104.38,4265.87 6110.53,4256.29
  region net CLDO2: 5795,5099.27 5785,5099.27 5785.14,5102.24 5784.15,5104.77 5795.85,5104.77 5794.86,5102.24
  region net CLDO2: 3851.5,5594.73 3861.5,5594.73 3861.36,5591.76 3862.35,5589.23 3850.65,5589.23 3851.64,5591.76
  region net AP-RESET: 4234.27,4988 4234.27,4994 4239.77,4996.85 4239.77,4985.15
  region net CLDO3: 5636.86,5514.36 5647.46,5524.96 5654.37,5518.55 5643.27,5507.45
  region net DCDC4: 5937,4500.77 5927,4500.77 5927.14,4503.74 5926.15,4506.27 5937.85,4506.27 5936.86,4503.74
  region net DCDC4: 6934.32,4222.75 6927.25,4215.68 ccw(c6867.45,4155.88) 6902.15,4233 6917,4247.85 ccw(c6994.12,4282.55)
  region net DCDC4: 5418,4214.9 ccw(c5227.98,4214.9) 5353,4358 5424.05,4383 5503,4358 ccw(c5628.02,4214.9) 5438,4214.9
  region net DCDC4: 3737.36,6136 ccw(c3737.36,5632.45) 3552,6100.64 3577,6161 3672.71,6221.36 ccw(c3787.36,6389.55) 3787.36,6186
  region net DCDC4: 3533.12,5698.88 cw(c3597.77,5770.88) 3501,5770.88 3476,5695.88 3501,5620.88 cw(c3597.77,5620.88) 3533.12,5692.88
  region net DCDC4: 3965.93,6123.93 ccw(c3878,5809.71) 3878,6136 3943,6161
  region net DCDC4: 5929.3,5089.7 ccw(c5980.98,5088.34) 5944.43,5051.79 5902,5073
  region net CLDO3: 4852.61,4462.39 cw(c5004.71,4307.18) 5004.71,4524.5 4994.5,4549.5 cw(c4994.5,4624.5) 4919.5,4624.5 4894.5,4636.71 cw(c4677.22,4636.71) 4831.39,4483.61
  region net DCDC4: 5858.97,4493.61 cw(c5717.36,4662.08) 5717.36,4442 5820.64,4413.77 5858.39,4379.39 5879.61,4400.61 cw(c5916.36,4436.21) 5880.18,4472.39
  region net DCDC4: 5889.54,4263.54 5882.46,4256.46 ccw(c5869.1,4243.1) 5869.15,4262 5884,4276.85 ccw(c5902.9,4276.9)
  region net CLDO3: 3486.72,5497.86 3500.86,5483.72 ccw(c4137.43,4847.15) 3480,5462.15 3465.15,5477 ccw(c2850.15,6134.43)
  region net DCDC4: 5927,4511.5 5937,4511.5 ccw(c5956.32,4511.5) 5942.5,4498 5922.14,4494.4 ccw(c5894.49,4511.5)
  region net DCDC4: 6064.35,4565 ccw(c6064.35,4653.11) 6119,4584 6134,4550
  region net DCDC4: 6578.71,4440.02 6593.08,4426.11 ccw(c7131.81,3887.38) 6572.29,4404.48 6557.3,4419 ccw(c5442.09,5576.63)
内层4:
  region net VDD-SYSFB: 3660,5602.76 3670,5602.76 3669.87,5599.79 3670.87,5597.25 3659.13,5597.25 3660.13,5599.79
  region net PWRON: 3698.73,5403.51 3694.49,5399.27 3688.56,5401.14 3696.86,5409.44
  region net RGMII0-RXD3: 6065.8,4504.47 6062.98,4507.29 6064.27,4510.29 6064.14,4513.93 6072.44,4505.63 6068.8,4505.76
  region net RGMII0-RXD2: 6049,4502.73 6045,4502.73 6043.79,4505.76 6041.13,4508.24 6052.87,4508.24 6050.21,4505.76
  region net RGMII0-RXD2: 6032.17,5432.66 6032.75,5426.42 6029.23,5427.45 6025.72,5427.19 6029.88,5438.16 6030.73,5435.09
  region net RGMII0-RXD3: 6012.22,5428.33 6009.39,5425.5 6006.39,5426.79 6002.76,5426.67 6011.06,5434.97 6010.93,5431.33
  region net CPUX-RX: 5832.55,5128.28 5835.38,5125.45 5834.09,5122.45 5834.21,5118.82 5825.91,5127.12 5829.55,5126.99
  region net CPUX-TX: 5832.55,5147.95 5835.38,5145.12 5834.09,5142.12 5834.21,5138.49 5825.91,5146.79 5829.55,5146.66
  region net LCD0-D21: 5953.84,5112.72 5950.3,5109.18 5947.44,5110.56 5944.02,5110.7 5952.32,5119 5952.46,5115.58
  region net HTXCN: 5062,4342.87 5066,4342.87 5067.21,4340.28 5069.87,4338.25 5058.13,4338.25 5060.79,4340.28
  region net HTXCP: 5083,4342.87 5087,4342.87 5088.21,4340.28 5090.87,4338.25 5079.13,4338.25 5081.79,4340.28
  region net HTX0N: 5119,4342.87 5123,4342.87 5124.21,4340.28 5126.87,4338.25 5115.13,4338.25 5117.79,4340.28
  region net HTX0P: 5139,4342.87 5143,4342.87 5144.21,4340.28 5146.87,4338.25 5135.13,4338.25 5137.79,4340.28
  region net HTX1N: 5175,4341.87 5179,4341.87 5180.21,4339.28 5182.87,4337.25 5171.13,4337.25 5173.79,4339.28
  region net HTX1P: 5195,4340.87 5199,4340.87 5200.57,4338.92 5202.87,4337.25 5191.13,4337.25 5193.43,4338.92
  region net HTX2N: 5234,4341.87 5238,4341.87 5239.21,4339.28 5241.87,4337.25 5230.13,4337.25 5232.79,4339.28
  region net HTX2P: 5254.66,4341.87 5258.66,4341.87 5259.87,4339.28 5262.53,4337.25 5250.79,4337.25 5253.45,4339.28
  region net HTX2P: 6321.41,5184.41 6318.59,5181.59 6316.23,5181.72 6313.56,5181.14 6321.86,5189.44 6321.28,5186.77
  region net HTX2N: 6318.59,5176.41 6321.41,5173.59 6321.28,5171.23 6321.86,5168.56 6313.56,5176.86 6316.23,5176.28
  region net HTX1P: 6310.32,5145 6302.79,5141 6300.16,5140.96 6297.27,5140.13 6304.81,5149.01 6307.13,5146.76
  region net HTX1N: 6303.59,5135.41 6306.41,5132.59 6305.43,5129.89 6305.86,5126.56 6297.56,5134.86 6300.89,5134.43
  region net HTX0N: 6287.59,5099.41 6290.41,5096.59 6289.43,5093.89 6289.86,5090.56 6281.56,5098.86 6284.89,5098.43
  region net HTX0P: 6295.32,5108.02 6287.81,5104.02 6285.18,5103.97 6282.29,5103.13 6289.81,5112.02 6292.13,5109.78
  region net HTXCP: 6317.41,5062.41 6314.59,5059.59 6311.89,5060.57 6308.56,5060.14 6316.86,5068.44 6316.43,5065.11
  region net HTXCN: 6314.59,5054.41 6317.41,5051.59 6316.43,5048.89 6316.86,5045.56 6308.56,5053.86 6311.89,5053.43
  region net LCD0-D17: 5840.24,4909.5 5840.24,4914.5 5843.24,4915.55 5845.75,4917.87 5845.75,4906.13 5843.24,4908.45
  region net LCD0-D16: 5841.5,4965.24 5836.5,4965.24 5835.45,4968.24 5833.13,4970.75 5844.87,4970.75 5842.55,4968.24
  region net LCD0-D16: 4495.76,4573.5 4495.76,4568.5 4492.76,4567.45 4490.25,4565.13 4490.25,4576.87 4492.76,4574.55
  region net LCD0-D17: 4510.76,4557.5 4510.76,4552.5 4507.76,4551.45 4505.25,4549.13 4505.25,4560.87 4507.76,4558.55
  region net LCD0-D18: 4523.76,4541.5 4523.76,4536.5 4520.76,4535.45 4518.25,4533.13 4518.25,4544.87 4520.76,4542.55
  region net LCD0-D21: 4563.84,4496.38 4567.38,4492.84 4566,4489.98 4565.86,4486.56 4557.56,4494.86 4560.98,4495
  region net LCD0-D18: 5946.5,5088.24 5941.5,5088.24 5940.45,5091.24 5938.13,5093.75 5949.87,5093.75 5947.55,5091.24
  region net LCD0-D19: 5974.21,4850.5 5966.67,4855.5 5969.88,4856.99 5972.19,4858.98 5979.73,4850.13
  region net LCD0-D19: 5892.76,4855.5 5892.76,4850.5 5889.76,4849.45 5887.25,4847.13 5887.25,4858.87 5889.76,4856.55
  region net USB0-VBUSDET: 6939.51,6112.27 6935.27,6116.51 6937.14,6122.44 6945.44,6114.14
  region net SDC2-DS: 4915.76,4814.5 4915.76,4809.5 4912.76,4808.45 4910.25,4806.13 4910.25,4817.87 4912.76,4815.55
  region net SDC2-DS: 5744.5,5128.16 5739.5,5128.16 5738.45,5131.16 5736.13,5133.68 5747.87,5133.68 5745.55,5131.16
  region net VDD-SYSFB: 5827.65,5344.73 5816.09,5347.31 5818.24,5349.65 5819.36,5351.82 5830.55,5349.6
  region net GM0_LED2: 5797.12,4373.88 5792.88,4378.12 5793.54,4380.05 5793.16,4382.44 5801.44,4374.16 5799.05,4374.54
  region net GM0_LED1: 5825,4383.27 5819,4383.27 5816.15,4388.77 5827.85,4388.77
  region net GM0_LED1: 5621.29,3709.39 5625.54,3713.63 5631.44,3711.76 5623.16,3703.49
  region net GM0_LED2: 5598.29,3709.15 5602.54,3713.39 5608.44,3711.52 5600.16,3703.25
  region net CPUX-RX: 6290,5250 6290,5254 6291.52,5255.56 6292.77,5257.85 6292.77,5246.15 6291.52,5248.44
  region net CPUX-TX: 6277.65,5253.82 6270.35,5252.18 6271.58,5255.78 6271.17,5259.13 6282.6,5256.64 6279.77,5255.47
  region net CAN-TX0: 5114.17,6021 5117,6018.17 5115.71,6015.18 5115.84,6011.56 5107.56,6019.84 5111.18,6019.71
  region net CAN-RX0: 5093.17,6022 5096,6019.17 5094.71,6016.18 5094.84,6012.56 5086.56,6020.84 5090.18,6020.71
  region net IR-RX: 5069.46,6023.71 5073.71,6019.46 5071.84,6013.56 5063.56,6021.84
  region net USB0-VBUSDET: 5033.46,6024.71 5037.71,6020.46 5035.84,6014.56 5027.56,6022.84
  region net USB0-DRVVBUS: 5010.46,6024.71 5014.71,6020.46 5012.84,6014.56 5004.56,6022.84
  region net CAN-TX0: 7071.27,4458 7071.27,4462 7074.3,4463.2 7076.77,4465.85 7076.77,4454.15 7074.3,4456.8
  region net CAN-RX0: 7227,4317.73 7231,4317.73 7232.2,4314.7 7234.85,4312.23 7223.15,4312.23 7225.8,4314.7
  region net IR-RX: 7057.46,4103.71 7061.71,4099.46 7059.84,4093.56 7051.56,4101.84
  region net USB0-DRVVBUS: 7012.29,6029.46 7016.54,6033.71 7022.44,6031.84 7014.16,6023.56
  region net PWRON: 4269.29,5376.46 4273.54,5380.71 4279.44,5378.84 4271.16,5370.56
